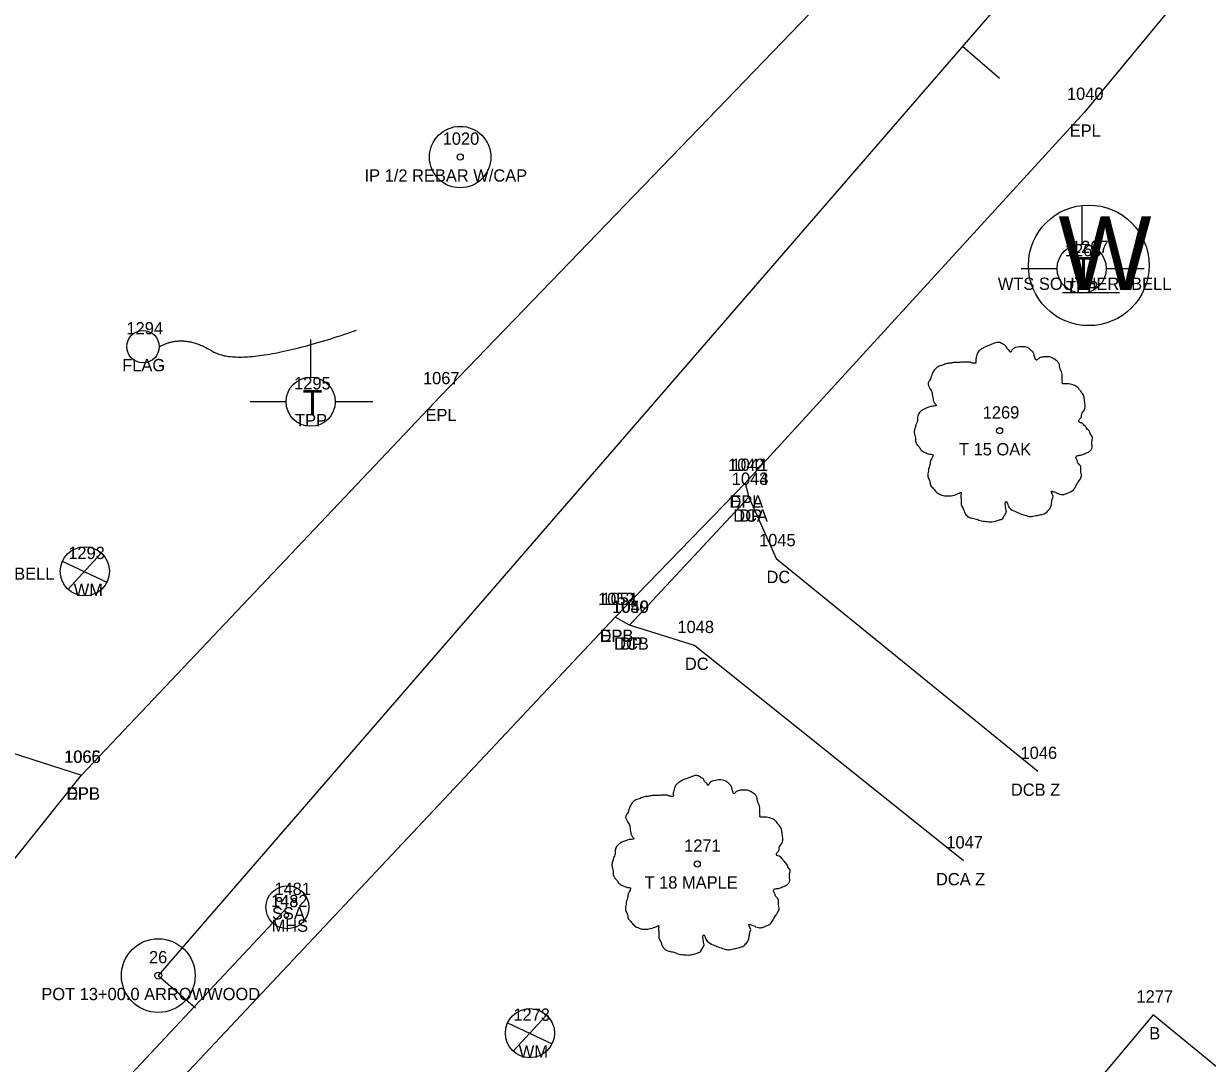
# Model space of a CAD drawing. Extents: x 1812340 to 1815011, y 1177659 to 1180159.
# Drawn here: x 1813840.8 to 1813937.1, y 1178204.5 to 1178289.1 of the extents above; entities that cross this region are included whole.
import ezdxf

# ---------------------------------------------------------------- set-up
doc = ezdxf.new("R2010")
doc.units = 0
for name, color, linetype in [('RD_EX_Bldg', 7, 'Continuous'), ('RD_EX_Bldg_txCode', 7, 'Continuous'), ('RD_EX_BldgApp_txCode', 7, 'Continuous'), ('RD_EX_Conc', 7, 'Continuous'), ('RD_EX_Conc_txCode', 7, 'Continuous'), ('RD_EX_DR_Inlet', 7, 'Continuous'), ('RD_EX_Driveway', 7, 'Continuous'), ('RD_EX_Driveway_txCode', 7, 'Continuous'), ('RD_EX_DV_Prop_txCode', 7, 'Continuous'), ('RD_EX_DV_PropPin', 7, 'Continuous'), ('RD_EX_Misc_txCode', 7, 'Continuous'), ('RD_EX_Road', 7, 'Continuous'), ('RD_EX_Road_txCode', 7, 'Continuous'), ('RD_EX_SU_Telecom', 7, 'Continuous'), ('RD_EX_UT', 7, 'Continuous'), ('RD_EX_UT_txCode', 7, 'Continuous'), ('RD_EX_VEG', 7, 'Continuous'), ('RD_EX_VEG_txCode', 7, 'Continuous'), ('RD_HC_CL', 7, 'Continuous'), ('RD_HC_Data', 7, 'Continuous'), ('RD_HC_Data_Tic', 7, 'Continuous'), ('RD_HC_txCode', 7, 'Continuous'), ('RD_SMD_Locator', 7, 'Continuous')]:
    doc.layers.add(name, color=color, linetype=linetype)

msp = doc.modelspace()

# ---------------------------------------------------------------- linework, layer by layer
at = {"layer": 'RD_EX_Bldg'}
msp.add_lwpolyline([(1813952.832, 1178191.893), (1813932.672, 1178208.432), (1813902.972, 1178172.996), (1813922.899, 1178156.295), (1813952.832, 1178191.893)], dxfattribs=at)
at = {"layer": 'RD_EX_Conc'}
for points in [[(1813899.789, 1178250.559), (1813902.004, 1178245.566), (1813923.302, 1178228.255)], [(1813917.241, 1178220.974), (1813895.365, 1178238.498), (1813890.08, 1178240.143)]]:
    msp.add_lwpolyline(points, dxfattribs=at)
at = {"layer": 'RD_EX_DR_Inlet'}
for centre, radius in [((1813862.254, 1178217.188), 1.75), ((1813861.59, 1178217.818), 0.175), ((1813862.814, 1178217.748), 0.175), ((1813862.167, 1178216.524), 0.175)]:
    msp.add_circle(centre, radius, dxfattribs=at)
at = {"layer": 'RD_EX_Driveway'}
for points in [[(1813899.481, 1178251.693), (1813899.789, 1178250.559), (1813890.08, 1178240.143), (1813888.904, 1178240.782)], [(1813830.807, 1178209.56), (1813824.507, 1178217.833), (1813834.858, 1178231.349), (1813845.508, 1178227.941)]]:
    msp.add_lwpolyline(points, dxfattribs=at)
at = {"layer": 'RD_EX_DV_PropPin'}
for radius in [2.499, 0.25]:
    msp.add_circle((1813876.306, 1178278.231), radius, dxfattribs=at)
at = {"layer": 'RD_EX_Road'}
for points in [[(1813829.874, 1178208.601), (1813830.807, 1178209.56), (1813845.508, 1178227.941), (1813874.688, 1178258.743), (1813910.021, 1178295.379), (1813943.631, 1178333.838), (1813974.312, 1178373.085), (1814001.91, 1178410.559), (1814011.897, 1178425.948), (1814015.579, 1178434.302), (1814016.708, 1178442.084), (1814017.031, 1178447.133), (1814015.195, 1178453.669), (1813986.469, 1178480.846), (1813949.155, 1178515.863)], [(1814062.161, 1178410.758), (1814056.57, 1178415.985), (1814052.145, 1178418.064), (1814044.495, 1178417.459), (1814039.532, 1178416.2), (1814027.176, 1178402.169), (1814022.797, 1178396.983), (1813991.686, 1178360.575), (1813959.638, 1178321.242), (1813927.093, 1178281.882), (1813899.481, 1178251.693), (1813888.904, 1178240.782), (1813846.632, 1178195.786)]]:
    msp.add_lwpolyline(points, dxfattribs=at)
at = {"layer": 'RD_EX_SU_Telecom'}
msp.add_circle((1813850.503, 1178262.801), 1.32, dxfattribs=at)
msp.add_open_spline([(1813851.823, 1178262.801), (1813853.827, 1178263.9), (1813858.509, 1178260.95), (1813867.873, 1178264.131)], degree=2, dxfattribs=at)
at = {"layer": 'RD_EX_UT'}
for p, q in [((1813926.866, 1178274.223), (1813926.866, 1178271.153)), ((1813921.936, 1178269.168), (1813924.866, 1178269.168)), ((1813928.866, 1178269.168), (1813931.936, 1178269.168)), ((1813925.311, 1178267.211), (1813929.941, 1178267.211)), ((1813864.142, 1178263.391), (1813864.142, 1178260.322)), ((1813859.211, 1178258.337), (1813862.142, 1178258.337)), ((1813866.142, 1178258.337), (1813869.211, 1178258.337)), ((1813843.935, 1178245.358), (1813847.566, 1178243.646)), ((1813844.417, 1178243.063), (1813847.084, 1178245.96)), ((1813862.261, 1178217.196), (1813843.967, 1178197.681)), ((1813880.627, 1178205.49), (1813883.294, 1178208.387)), ((1813880.146, 1178207.786), (1813883.776, 1178206.073))]:
    msp.add_line(p, q, dxfattribs=at)
for centre, radius in [((1813927.44, 1178269.419), 4.908), ((1813926.866, 1178269.153), 2), ((1813864.142, 1178258.322), 2), ((1813845.769, 1178244.521), 2), ((1813881.979, 1178206.948), 2)]:
    msp.add_circle(centre, radius, dxfattribs=at)
at = {"layer": 'RD_EX_VEG'}
for centre, radius in [((1813920.186, 1178255.954), 0.25), ((1813920.174, 1178255.935), 0.0001), ((1813895.589, 1178220.705), 0.25), ((1813895.576, 1178220.686), 0.0001)]:
    msp.add_circle(centre, radius, dxfattribs=at)
for points in [[(1813920.318, 1178263.121), (1813920.018, 1178263.146), (1813919.694, 1178263.046), (1813919.444, 1178262.946), (1813919.219, 1178262.871), (1813918.994, 1178262.771), (1813918.694, 1178262.597), (1813918.469, 1178262.397), (1813918.344, 1178262.147), (1813918.294, 1178261.922), (1813918.244, 1178261.647), (1813918.244, 1178261.472), (1813918.119, 1178261.447), (1813917.969, 1178261.472), (1813917.719, 1178261.547), (1813917.469, 1178261.547), (1813917.22, 1178261.547), (1813916.87, 1178261.522), (1813916.52, 1178261.522), (1813916.245, 1178261.472), (1813915.92, 1178261.422), (1813915.545, 1178261.297), (1813915.195, 1178261.172), (1813914.896, 1178260.922), (1813914.646, 1178260.448), (1813914.521, 1178260.098), (1813914.371, 1178259.848), (1813914.521, 1178259.398), (1813914.696, 1178259.048), (1813914.721, 1178258.848), (1813914.796, 1178258.423), (1813914.896, 1178258.199), (1813915.021, 1178257.999), (1813914.946, 1178257.974), (1813914.571, 1178257.924), (1813914.271, 1178257.824), (1813913.846, 1178257.599), (1813913.621, 1178257.374), (1813913.521, 1178257.049), (1813913.496, 1178256.699), (1813913.396, 1178256.499), (1813913.321, 1178256.224), (1813913.296, 1178256.149), (1813913.246, 1178255.825), (1813913.346, 1178255.375), (1813913.371, 1178255.025), (1813913.496, 1178254.8), (1813913.646, 1178254.625), (1813913.821, 1178254.375), (1813914.221, 1178254.15), (1813914.546, 1178254.05), (1813914.746, 1178254.025), (1813914.571, 1178253.526), (1813914.521, 1178253.176), (1813914.396, 1178252.776), (1813914.396, 1178252.701), (1813914.346, 1178252.226), (1813914.496, 1178251.901), (1813914.571, 1178251.526), (1813914.746, 1178251.302), (1813915.021, 1178251.002), (1813915.345, 1178250.777), (1813915.845, 1178250.652), (1813916.245, 1178250.677), (1813916.82, 1178250.852), (1813917.07, 1178250.927), (1813917.045, 1178250.752), (1813917.07, 1178250.377), (1813917.07, 1178249.952), (1813917.22, 1178249.627), (1813917.32, 1178249.352), (1813917.469, 1178249.102), (1813917.794, 1178248.878), (1813918.194, 1178248.803), (1813918.619, 1178248.653), (1813919.069, 1178248.578), (1813919.569, 1178248.553), (1813920.168, 1178248.703), (1813920.443, 1178248.828), (1813920.543, 1178249.003), (1813920.743, 1178249.377), (1813920.693, 1178249.602), (1813920.718, 1178250.202), (1813920.818, 1178250.027), (1813920.993, 1178249.677), (1813921.493, 1178249.377), (1813921.893, 1178249.202), (1813922.367, 1178249.052), (1813922.667, 1178248.978), (1813923.142, 1178249.052), (1813923.517, 1178249.127), (1813923.892, 1178249.252), (1813924.192, 1178249.527), (1813924.366, 1178249.802), (1813924.416, 1178250.077), (1813924.491, 1178250.452), (1813924.541, 1178250.627)], [(1813924.541, 1178250.627), (1813924.466, 1178250.802), (1813924.416, 1178251.052), (1813924.491, 1178251.027), (1813924.666, 1178250.977), (1813924.941, 1178250.852), (1813925.166, 1178250.777), (1813925.491, 1178250.802), (1813925.766, 1178250.902), (1813926.216, 1178251.177), (1813926.491, 1178251.651), (1813926.765, 1178252.051), (1813926.84, 1178252.376), (1813926.79, 1178252.601), (1813926.765, 1178253.101), (1813926.565, 1178253.351), (1813926.515, 1178253.476), (1813926.416, 1178253.875), (1813926.491, 1178253.925), (1813926.765, 1178253.975), (1813927.14, 1178254.1), (1813927.415, 1178254.225), (1813927.64, 1178254.4), (1813927.715, 1178254.625), (1813927.69, 1178255.025), (1813927.74, 1178255.425), (1813927.665, 1178255.575), (1813927.565, 1178255.725), (1813927.49, 1178255.925), (1813927.34, 1178256.074), (1813927.24, 1178256.224), (1813927.14, 1178256.324), (1813927.015, 1178256.474), (1813926.84, 1178256.599), (1813926.69, 1178256.649), (1813926.64, 1178256.799), (1813926.79, 1178256.999), (1813926.84, 1178257.099), (1813926.865, 1178257.324), (1813927.09, 1178257.674), (1813927.14, 1178258.074), (1813927.09, 1178258.498), (1813927.04, 1178258.773), (1813926.89, 1178259.048), (1813926.69, 1178259.298), (1813926.565, 1178259.473), (1813926.391, 1178259.598), (1813926.066, 1178259.723), (1813925.816, 1178259.773), (1813925.466, 1178259.773), (1813925.266, 1178259.823), (1813925.291, 1178259.873), (1813925.291, 1178260.023), (1813925.291, 1178260.298), (1813925.216, 1178260.747), (1813925.066, 1178261.247), (1813925.066, 1178261.272), (1813924.966, 1178261.522), (1813924.741, 1178261.722), (1813924.566, 1178261.822), (1813924.366, 1178261.947), (1813924.117, 1178261.972), (1813923.817, 1178261.972), (1813923.542, 1178261.922), (1813923.342, 1178261.822), (1813923.167, 1178261.697), (1813923.092, 1178261.847), (1813922.992, 1178262.147), (1813922.942, 1178262.297), (1813922.792, 1178262.472), (1813922.567, 1178262.672), (1813922.117, 1178262.796), (1813921.493, 1178262.722), (1813921.193, 1178262.522), (1813921.043, 1178262.347), (1813920.993, 1178262.472), (1813920.793, 1178262.672), (1813920.693, 1178262.846), (1813920.518, 1178262.971), (1813920.368, 1178263.071), (1813920.268, 1178263.121)], [(1813895.721, 1178227.872), (1813895.421, 1178227.897), (1813895.096, 1178227.797), (1813894.846, 1178227.697), (1813894.621, 1178227.622), (1813894.396, 1178227.522), (1813894.096, 1178227.347), (1813893.871, 1178227.147), (1813893.746, 1178226.897), (1813893.696, 1178226.672), (1813893.646, 1178226.398), (1813893.646, 1178226.223), (1813893.522, 1178226.198), (1813893.372, 1178226.223), (1813893.122, 1178226.298), (1813892.872, 1178226.298), (1813892.622, 1178226.298), (1813892.272, 1178226.273), (1813891.922, 1178226.273), (1813891.647, 1178226.223), (1813891.322, 1178226.173), (1813890.948, 1178226.048), (1813890.598, 1178225.923), (1813890.298, 1178225.673), (1813890.048, 1178225.198), (1813889.923, 1178224.848), (1813889.773, 1178224.598), (1813889.923, 1178224.149), (1813890.098, 1178223.799), (1813890.123, 1178223.599), (1813890.198, 1178223.174), (1813890.298, 1178222.949), (1813890.423, 1178222.749), (1813890.348, 1178222.724), (1813889.973, 1178222.674), (1813889.673, 1178222.574), (1813889.248, 1178222.349), (1813889.023, 1178222.124), (1813888.923, 1178221.799), (1813888.899, 1178221.45), (1813888.799, 1178221.25), (1813888.724, 1178220.975), (1813888.699, 1178220.9), (1813888.649, 1178220.575), (1813888.749, 1178220.125), (1813888.774, 1178219.775), (1813888.899, 1178219.55), (1813889.048, 1178219.376), (1813889.223, 1178219.126), (1813889.623, 1178218.901), (1813889.948, 1178218.801), (1813890.148, 1178218.776), (1813889.973, 1178218.276), (1813889.923, 1178217.926), (1813889.798, 1178217.526), (1813889.798, 1178217.451), (1813889.748, 1178216.977), (1813889.898, 1178216.652), (1813889.973, 1178216.277), (1813890.148, 1178216.052), (1813890.423, 1178215.752), (1813890.748, 1178215.527), (1813891.248, 1178215.402), (1813891.647, 1178215.427), (1813892.222, 1178215.602), (1813892.472, 1178215.677), (1813892.447, 1178215.502), (1813892.472, 1178215.127), (1813892.472, 1178214.703), (1813892.622, 1178214.378), (1813892.722, 1178214.103), (1813892.872, 1178213.853), (1813893.197, 1178213.628), (1813893.596, 1178213.553), (1813894.021, 1178213.403), (1813894.471, 1178213.328), (1813894.971, 1178213.303), (1813895.571, 1178213.453), (1813895.845, 1178213.578), (1813895.945, 1178213.753), (1813896.145, 1178214.128), (1813896.095, 1178214.353), (1813896.12, 1178214.953), (1813896.22, 1178214.778), (1813896.395, 1178214.428), (1813896.895, 1178214.128), (1813897.295, 1178213.953), (1813897.77, 1178213.803), (1813898.07, 1178213.728), (1813898.544, 1178213.803), (1813898.919, 1178213.878), (1813899.294, 1178214.003), (1813899.594, 1178214.278), (1813899.769, 1178214.553), (1813899.819, 1178214.828), (1813899.894, 1178215.202), (1813899.944, 1178215.377)], [(1813899.944, 1178215.377), (1813899.869, 1178215.552), (1813899.819, 1178215.802), (1813899.894, 1178215.777), (1813900.069, 1178215.727), (1813900.344, 1178215.602), (1813900.568, 1178215.527), (1813900.893, 1178215.552), (1813901.168, 1178215.652), (1813901.618, 1178215.927), (1813901.893, 1178216.402), (1813902.168, 1178216.802), (1813902.243, 1178217.127), (1813902.193, 1178217.351), (1813902.168, 1178217.851), (1813901.968, 1178218.101), (1813901.918, 1178218.226), (1813901.818, 1178218.626), (1813901.893, 1178218.676), (1813902.168, 1178218.726), (1813902.543, 1178218.851), (1813902.817, 1178218.976), (1813903.042, 1178219.151), (1813903.117, 1178219.376), (1813903.092, 1178219.775), (1813903.142, 1178220.175), (1813903.067, 1178220.325), (1813902.967, 1178220.475), (1813902.892, 1178220.675), (1813902.742, 1178220.825), (1813902.643, 1178220.975), (1813902.543, 1178221.075), (1813902.418, 1178221.225), (1813902.243, 1178221.35), (1813902.093, 1178221.4), (1813902.043, 1178221.55), (1813902.193, 1178221.75), (1813902.243, 1178221.849), (1813902.268, 1178222.074), (1813902.493, 1178222.424), (1813902.543, 1178222.824), (1813902.493, 1178223.249), (1813902.443, 1178223.524), (1813902.293, 1178223.799), (1813902.093, 1178224.049), (1813901.968, 1178224.223), (1813901.793, 1178224.348), (1813901.468, 1178224.473), (1813901.218, 1178224.523), (1813900.868, 1178224.523), (1813900.668, 1178224.573), (1813900.693, 1178224.623), (1813900.693, 1178224.773), (1813900.693, 1178225.048), (1813900.618, 1178225.498), (1813900.468, 1178225.998), (1813900.468, 1178226.023), (1813900.368, 1178226.273), (1813900.144, 1178226.472), (1813899.969, 1178226.572), (1813899.769, 1178226.697), (1813899.519, 1178226.722), (1813899.219, 1178226.722), (1813898.944, 1178226.672), (1813898.744, 1178226.572), (1813898.569, 1178226.447), (1813898.494, 1178226.597), (1813898.394, 1178226.897), (1813898.344, 1178227.047), (1813898.194, 1178227.222), (1813897.97, 1178227.422), (1813897.52, 1178227.547), (1813896.895, 1178227.472), (1813896.595, 1178227.272), (1813896.445, 1178227.097), (1813896.395, 1178227.222), (1813896.195, 1178227.422), (1813896.095, 1178227.597), (1813895.92, 1178227.722), (1813895.771, 1178227.822), (1813895.671, 1178227.872)]]:
    msp.add_spline(points, degree=3, dxfattribs=at)
at = {"layer": 'RD_HC_CL'}
msp.add_line((1814048.019, 1178438.511), (1813851.744, 1178211.627), dxfattribs=at)
at = {"layer": 'RD_HC_Data'}
for radius in [3, 0.282]:
    msp.add_circle((1813851.744, 1178211.627), radius, dxfattribs=at)
at = {"layer": 'RD_HC_Data_Tic'}
for p, q in [((1813917.169, 1178287.255), (1813920.194, 1178284.638)), ((1813851.744, 1178211.627), (1813854.769, 1178209.01))]:
    msp.add_line(p, q, dxfattribs=at)
at = {"layer": 'RD_SMD_Locator'}
for centre in [(1813927.093, 1178281.882), (1813874.688, 1178258.743), (1813899.481, 1178251.693), (1813899.481, 1178251.693), (1813899.789, 1178250.559), (1813899.789, 1178250.559), (1813902.004, 1178245.566), (1813888.904, 1178240.782), (1813888.904, 1178240.782), (1813890.08, 1178240.143), (1813890.08, 1178240.143), (1813895.365, 1178238.498), (1813923.302, 1178228.255), (1813845.508, 1178227.941), (1813845.508, 1178227.941), (1813917.241, 1178220.974), (1813862.261, 1178217.196), (1813851.744, 1178211.627), (1813932.672, 1178208.432)]:
    msp.add_circle(centre, 0.001, dxfattribs=at)

# ---------------------------------------------------------------- texts
at = {"layer": 'RD_EX_Bldg_txCode'}
for s, p in [('1277', (1813931.326, 1178209.432)), ('B', (1813932.365, 1178206.432))]:
    msp.add_text(s, height=1, dxfattribs=at).set_placement(p)
at = {"layer": 'RD_EX_BldgApp_txCode'}
for s, p in [('1294', (1813849.156, 1178263.801)), ('FLAG', (1813848.81, 1178260.801))]:
    msp.add_text(s, height=1, dxfattribs=at).set_placement(p)
at = {"layer": 'RD_EX_Conc_txCode'}
for s, p in [('1044', (1813898.403, 1178251.559)), ('DCA', (1813898.521, 1178248.559)), ('1045', (1813900.618, 1178246.566)), ('DC', (1813901.225, 1178243.566)), ('1049', (1813888.694, 1178241.143)), ('1048', (1813893.979, 1178239.498)), ('DCB', (1813888.828, 1178238.143)), ('DC', (1813894.586, 1178236.498)), ('1046', (1813921.892, 1178229.255)), ('DCB Z', (1813921.105, 1178226.255)), ('1047', (1813915.855, 1178221.974)), ('DCA Z', (1813915.012, 1178218.974))]:
    msp.add_text(s, height=1, dxfattribs=at).set_placement(p)
at = {"layer": 'RD_EX_Driveway_txCode'}
for s, p in [('1042', (1813898.096, 1178252.693)), ('1043', (1813898.403, 1178251.559)), ('DPA', (1813898.214, 1178249.693)), ('DP', (1813899.01, 1178248.559)), ('1051', (1813887.802, 1178241.782)), ('1050', (1813888.655, 1178241.143)), ('DPB', (1813887.652, 1178238.782)), ('DP', (1813889.3, 1178238.143)), ('1065', (1813844.098, 1178228.941)), ('DPB', (1813844.256, 1178225.941))]:
    msp.add_text(s, height=1, dxfattribs=at).set_placement(p)
at = {"layer": 'RD_EX_DV_Prop_txCode'}
for s, p in [('1020', (1813874.881, 1178279.231)), ('IP 1/2 REBAR W/CAP', (1813868.527, 1178276.231))]:
    msp.add_text(s, height=1, dxfattribs=at).set_placement(p)
at = {"layer": 'RD_EX_Misc_txCode'}
msp.add_text('MSLA ORNAMENTAL BELL', height=1, dxfattribs=at).set_placement((1813826.352, 1178243.831))
at = {"layer": 'RD_EX_Road_txCode'}
for s, p in [('1040', (1813925.668, 1178282.882)), ('EPL', (1813925.888, 1178279.882)), ('1067', (1813873.279, 1178259.743)), ('EPL', (1813873.483, 1178256.743)), ('1041', (1813898.379, 1178252.693)), ('EPL', (1813898.277, 1178249.693)), ('1052', (1813887.518, 1178241.782)), ('EPL', (1813887.7, 1178238.782)), ('1066', (1813844.075, 1178228.941)), ('EPL', (1813844.303, 1178225.941))]:
    msp.add_text(s, height=1, dxfattribs=at).set_placement(p)
at = {"layer": 'RD_EX_UT'}
for s, height, p in [('W', 6, (1813924.975, 1178267.418)), ('T', 2, (1813926.197, 1178268.106)), ('T', 2, (1813863.473, 1178257.274))]:
    msp.add_text(s, height=height, dxfattribs=at).set_placement(p)
at = {"layer": 'RD_EX_UT_txCode'}
for s, p in [('1267', (1813926.07, 1178270.419)), ('1268', (1813925.496, 1178270.153)), ('WTS SOUTHERNBELL', (1813920.046, 1178267.419)), ('TPP', (1813925.599, 1178267.153)), ('1295', (1813862.796, 1178259.322)), ('TPP', (1813862.874, 1178256.322)), ('1293', (1813844.422, 1178245.521)), ('WM', (1813844.863, 1178242.521)), ('1481', (1813861.191, 1178218.188)), ('1482', (1813860.914, 1178217.196)), ('SSA', (1813860.993, 1178216.196)), ('MHS', (1813860.963, 1178215.188)), ('1273', (1813880.633, 1178207.948)), ('WM', (1813881.073, 1178204.948))]:
    msp.add_text(s, height=1, dxfattribs=at).set_placement(p)
at = {"layer": 'RD_EX_VEG_txCode'}
for s, p in [('1269', (1813918.816, 1178256.954)), ('T 15 OAK', (1813916.887, 1178253.954)), ('1271', (1813894.526, 1178221.705)), ('T 18 MAPLE', (1813891.301, 1178218.705))]:
    msp.add_text(s, height=1, dxfattribs=at).set_placement(p)
at = {"layer": 'RD_HC_txCode'}
for s, p in [('26', (1813850.988, 1178212.627)), ('POT 13+00.0 ARROWWOOD', (1813842.232, 1178209.627))]:
    msp.add_text(s, height=1, dxfattribs=at).set_placement(p)

doc.saveas('drawing.dxf')
